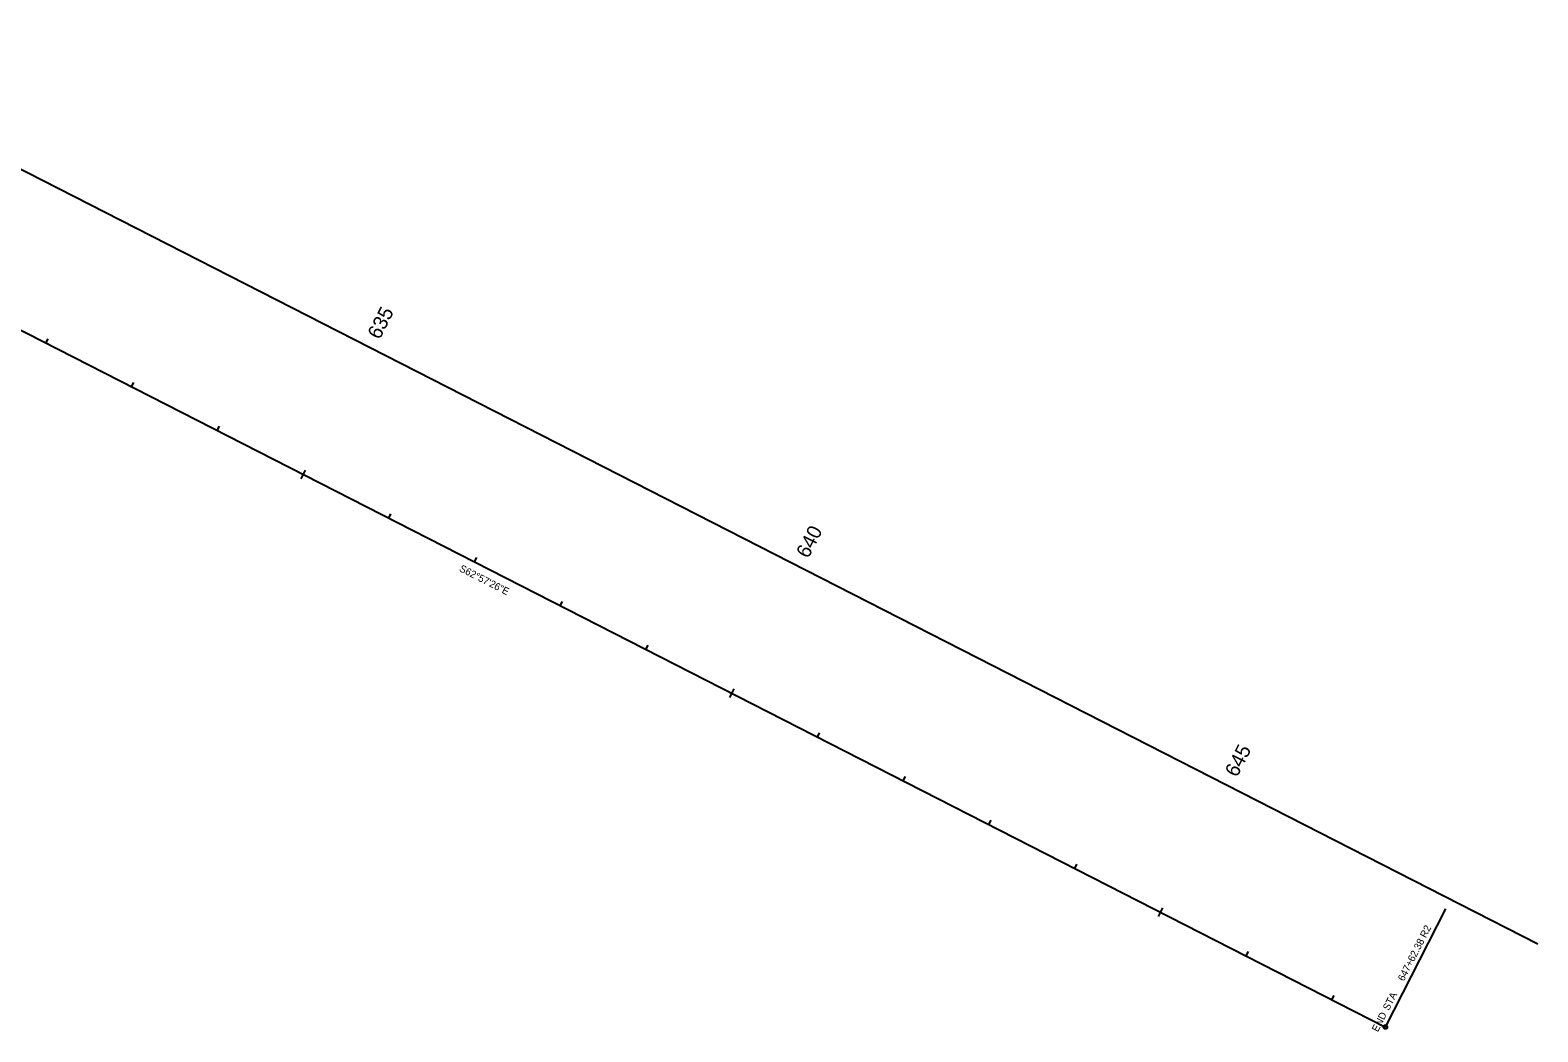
# Model space of a CAD drawing. Extents: x 1604882 to 1608571, y 865355 to 868094.
# Drawn here: x 1607005 to 1608571, y 865355 to 866395 of the extents above; entities that cross this region are included whole.
import ezdxf

# ---------------------------------------------------------------- set-up
doc = ezdxf.new("R2010")
doc.units = 0
for name, color, linetype in [('Default', 7, 'Continuous'), ('Modeling-Contours-Major-Existing', 7, 'Continuous'), ('Modeling-Contours-Minor-Existing', 7, 'Continuous'), ('Modeling-Flow Arrows-Existing', 7, 'Continuous'), ('Modeling-Spot-Existing', 7, 'Continuous'), ('Modeling-Triangle Verticies-Existing', 7, 'Continuous'), ('Modeling-Triangles-Existing', 7, 'Continuous')]:
    doc.layers.add(name, color=color, linetype=linetype)

msp = doc.modelspace()

# ---------------------------------------------------------------- linework, layer by layer
at = {"layer": 'Default'}
for p, q in [((1606712.2, 866394.9), (1608570.8, 865446.1)), ((1606554, 866308.3), (1608412.4, 865359.6))]:
    msp.add_line(p, q, dxfattribs=at)
at = {"layer": 'Modeling-Contours-Minor-Existing'}
for p, q in [((1607290.3, 865938), (1607285.8, 865929.1)), ((1607735.7, 865710.7), (1607731.1, 865701.8)), ((1608181, 865483.3), (1608176.5, 865474.4))]:
    msp.add_line(p, q, dxfattribs=at)
at = {"layer": 'Modeling-Spot-Existing'}
for p in [(1608412.4, 865359.6), (1608475.2, 865482.5)]:
    msp.add_line(p, (1608475.2, 865482.5), dxfattribs=at)
msp.add_circle((1608412.4, 865359.6), 1.98, dxfattribs=at)
at = {"layer": 'Modeling-Triangle Verticies-Existing'}
for p, q in [((1607020.9, 866070), (1607023.1, 866074.4)), ((1607109.9, 866024.5), (1607112.2, 866029)), ((1607199, 865979), (1607201.3, 865983.5)), ((1607377.1, 865888.1), (1607379.4, 865892.6)), ((1607466.2, 865842.6), (1607468.5, 865847.1)), ((1607555.3, 865797.2), (1607557.5, 865801.6)), ((1607644.3, 865751.7), (1607646.6, 865756.2)), ((1607822.5, 865660.8), (1607824.7, 865665.2)), ((1607911.5, 865615.3), (1607913.8, 865619.8)), ((1608000.6, 865569.8), (1608002.9, 865574.3)), ((1608089.7, 865524.4), (1608091.9, 865528.8)), ((1608267.8, 865433.4), (1608270.1, 865437.9)), ((1608356.9, 865388), (1608359.1, 865392.4))]:
    msp.add_line(p, q, dxfattribs=at)
at = {"layer": 'Modeling-Triangles-Existing'}
msp.add_line((1606572.7, 866298.7), (1608412.4, 865359.6), dxfattribs=at)

# ---------------------------------------------------------------- texts
at = {"layer": 'Modeling-Contours-Major-Existing'}
for s, p in [('635', (1607367.6, 866072.8)), ('640', (1607812.9, 865845.5)), ('645', (1608258.3, 865618.2))]:
    msp.add_text(s, height=15, rotation=62.9571, dxfattribs=at).set_placement(p)
at = {"layer": 'Modeling-Flow Arrows-Existing'}
msp.add_text('S62°57\'26"E', height=7.5, rotation=332.9571, dxfattribs=at).set_placement((1607449.7, 865833.4))
at = {"layer": 'Modeling-Spot-Existing'}
for s, p in [('647+62.38 R2', (1608431.6, 865406.6)), (' STA ', (1608414.7, 865373.6)), ('END', (1608404.6, 865353.9))]:
    msp.add_text(s, height=7.5, rotation=62.9571, dxfattribs=at).set_placement(p)

doc.saveas('drawing.dxf')
